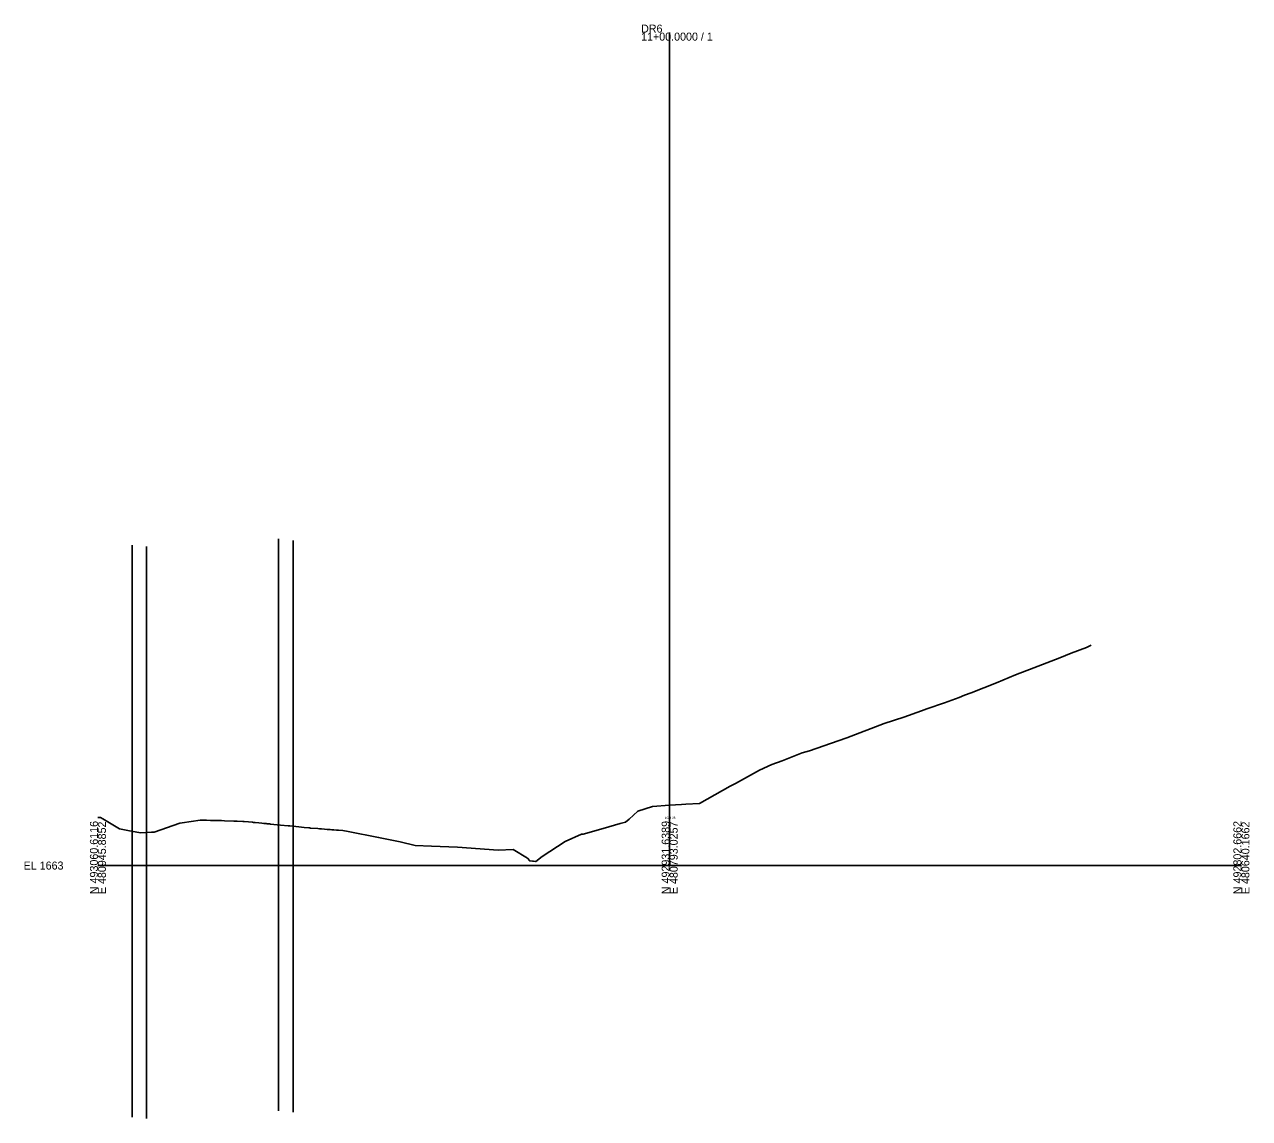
# Model space of a CAD drawing. Extents: x -26 to 403, y -88 to 5647.
# Drawn here: x -25.7 to 402.8, y 1911.5 to 2294.2 of the extents above; entities that cross this region are included whole.
import ezdxf

# ---------------------------------------------------------------- set-up
doc = ezdxf.new("R2010")
doc.units = 0
for name, color, linetype in [('Exist Cross Section Cell', 7, 'Continuous'), ('Exist XS Center Line Elevation Label', 7, 'Continuous'), ('Exist XS Ground Line', 7, 'Continuous'), ('Scratch_Level_7', 7, 'Continuous')]:
    doc.layers.add(name, color=color, linetype=linetype)

msp = doc.modelspace()

# ---------------------------------------------------------------- linework, layer by layer
at = {"layer": 'Exist Cross Section Cell'}
for p, q in [((200, 2000), (200, 2291.33)), ((0, 2000), (200, 2000)), ((200, 2000), (400, 2000))]:
    msp.add_line(p, q, dxfattribs=at)
at = {"layer": 'Exist XS Ground Line'}
msp.add_lwpolyline([(0, 2016.79), (0.93, 2016.82), (1.7, 2016.36), (7.54, 2012.8), (10.45, 2012.29), (14.91, 2011.43), (18.73, 2011.63), (19.67, 2011.72), (28.65, 2014.85), (29.42, 2014.96), (35.73, 2015.9), (37.17, 2015.89), (37.5, 2015.88), (37.95, 2015.87), (39.43, 2015.82), (40.28, 2015.8), (41.03, 2015.77), (42.08, 2015.74), (43.28, 2015.71), (44.26, 2015.67), (47.52, 2015.57), (48.38, 2015.55), (48.73, 2015.53), (50.74, 2015.44), (51.14, 2015.41), (52.69, 2015.27), (54.02, 2015.13), (54.46, 2015.09), (54.99, 2015.04), (56.25, 2014.92), (57.33, 2014.81), (58.03, 2014.74), (58.85, 2014.67), (59.21, 2014.64), (59.97, 2014.57), (60.39, 2014.53), (62.71, 2014.29), (63.86, 2014.17), (66.58, 2013.89), (67.11, 2013.84), (69.22, 2013.62), (70.3, 2013.52), (72.19, 2013.33), (73.72, 2013.19), (74.04, 2013.16), (74.38, 2013.14), (76.9, 2012.93), (77.47, 2012.89), (78.18, 2012.82), (79.31, 2012.72), (80.22, 2012.66), (81.27, 2012.59), (81.83, 2012.55), (82.5, 2012.5), (83.51, 2012.42), (84.2, 2012.35), (85.67, 2012.21), (87.55, 2011.86), (98.17, 2009.85), (105.67, 2008.35), (110.97, 2007.07), (116.72, 2006.83), (125.75, 2006.4), (140.01, 2005.34), (145.27, 2005.65), (150.21, 2002.55), (151.08, 2001.65), (151.96, 2001.59), (152.36, 2001.57), (153.17, 2001.38), (155.38, 2003.17), (163.49, 2008.42), (169.19, 2010.97), (169.7, 2011.04), (176.78, 2012.95), (182.69, 2014.77), (184.6, 2015.18), (185.85, 2016.28), (188.84, 2019), (193.95, 2020.71), (200, 2021.08), (204.1, 2021.33), (205.7, 2021.42), (210.4, 2021.74), (221.21, 2027.76), (223.03, 2028.73), (231.44, 2033.39), (235.79, 2035.36), (239.31, 2036.66), (243.48, 2038.22), (246.41, 2039.41), (248.88, 2040.13), (258.99, 2043.59), (261.96, 2044.63), (275.05, 2049.68), (281.9, 2051.88), (288.14, 2054.13), (289, 2054.43), (290.01, 2054.82), (296.09, 2056.97), (301.22, 2058.8), (303.19, 2059.55), (305.52, 2060.39), (314.31, 2063.87), (321.03, 2066.67), (327.4, 2069.17), (336.54, 2072.67), (340.48, 2074.27), (345.78, 2076.31), (347.44, 2077.11)], dxfattribs=at)
at = {"layer": 'Scratch_Level_7'}
for p, q in [((63.22, 2114.24), (63.22, 1914.24)), ((68.24, 2113.72), (68.24, 1913.72)), ((11.93, 2112.01), (11.93, 1912.01)), ((16.94, 2111.54), (16.94, 1911.54))]:
    msp.add_line(p, q, dxfattribs=at)

# ---------------------------------------------------------------- texts
at = {"layer": 'Exist Cross Section Cell'}
for s, p in [('DR6', (190, 2291.33)), ('11+00.0000 / 1', (190, 2288.53)), ('EL 1663', (-26, 1998.6))]:
    msp.add_text(s, height=2.8, dxfattribs=at).set_placement(p)
for s, p in [('N 493060.6116', (0, 1990)), ('E 480945.8852', (2.8, 1990)), ('N 492931.6389', (200, 1990)), ('E 480793.0257', (202.8, 1990)), ('N 492802.6662', (400, 1990)), ('E 480640.1662', (402.8, 1990))]:
    msp.add_text(s, height=2.8, rotation=90, dxfattribs=at).set_placement(p)
at = {"layer": 'Exist XS Center Line Elevation Label'}
msp.add_text('1684.08', height=0.75, dxfattribs=at).set_placement((198.26, 2016.33))

doc.saveas('drawing.dxf')
